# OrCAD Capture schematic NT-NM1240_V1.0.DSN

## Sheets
1 Nu-Link-ME V3.0: size A4; title: Nu-Link-Me; rev: 3.0; note: 1
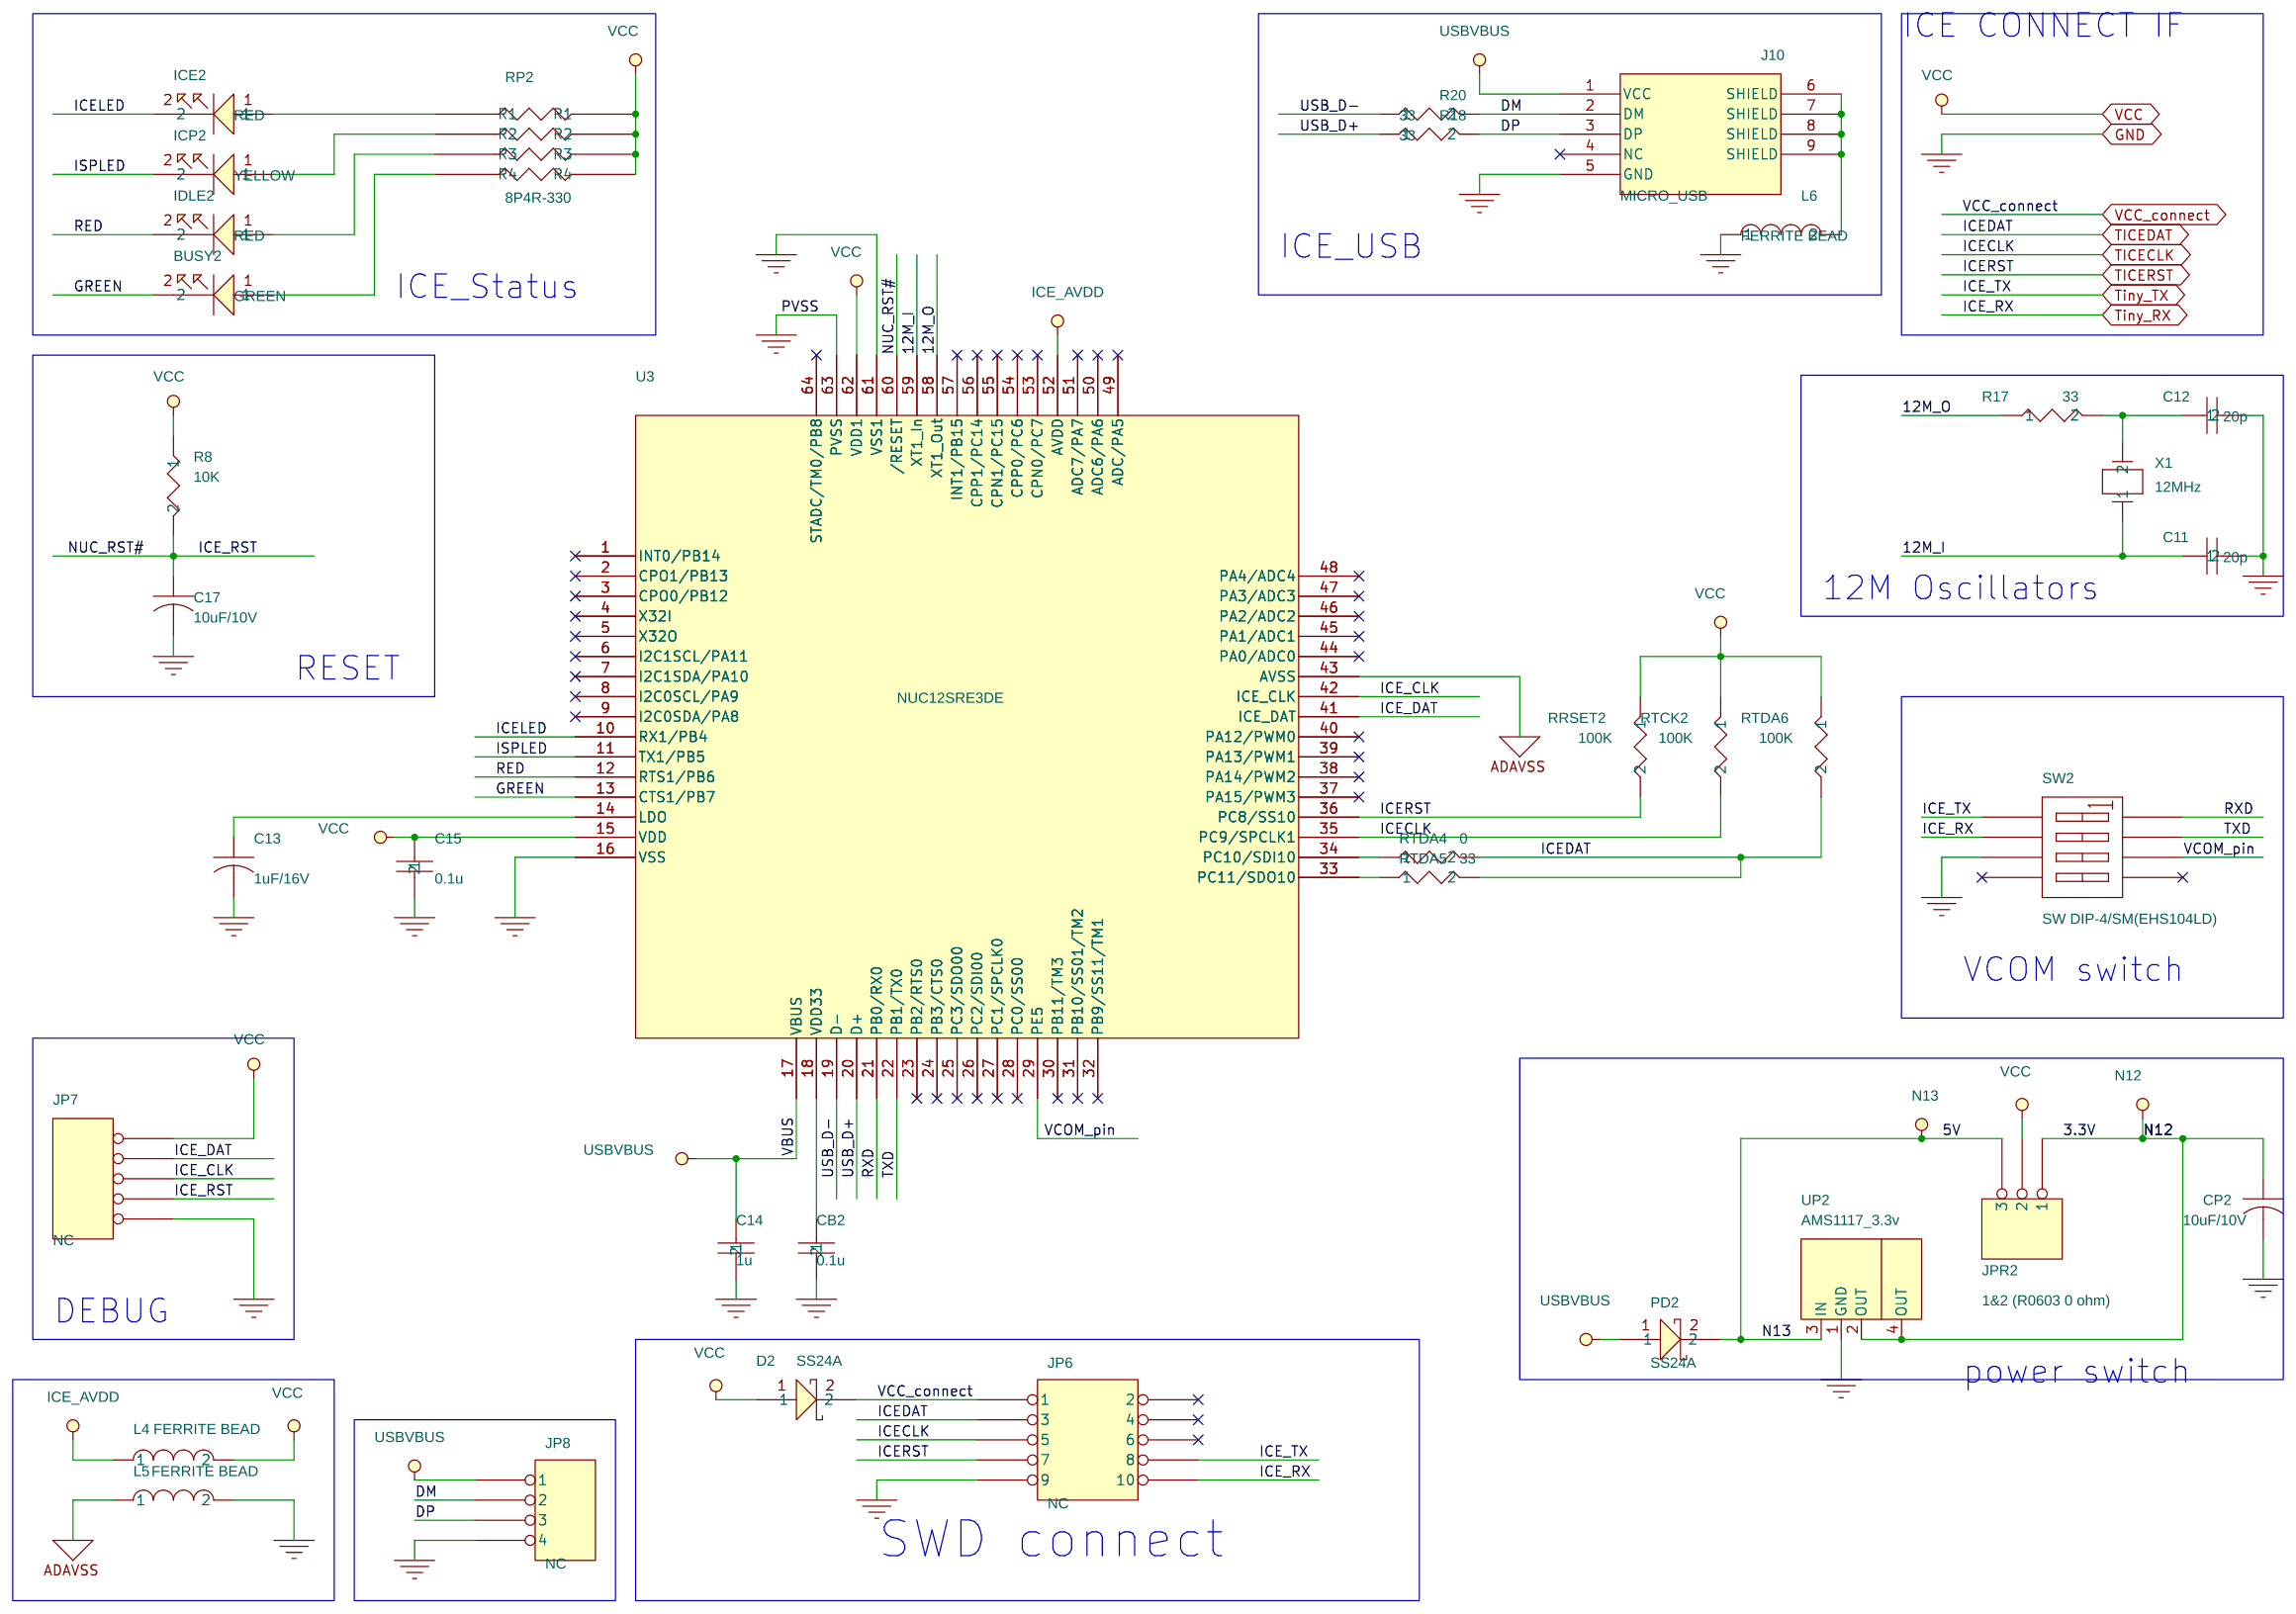
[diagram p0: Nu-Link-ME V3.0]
2 NuTiny-NM1240: size A3; title: NuTiny-EVB-NM1244D48; rev: V1.0
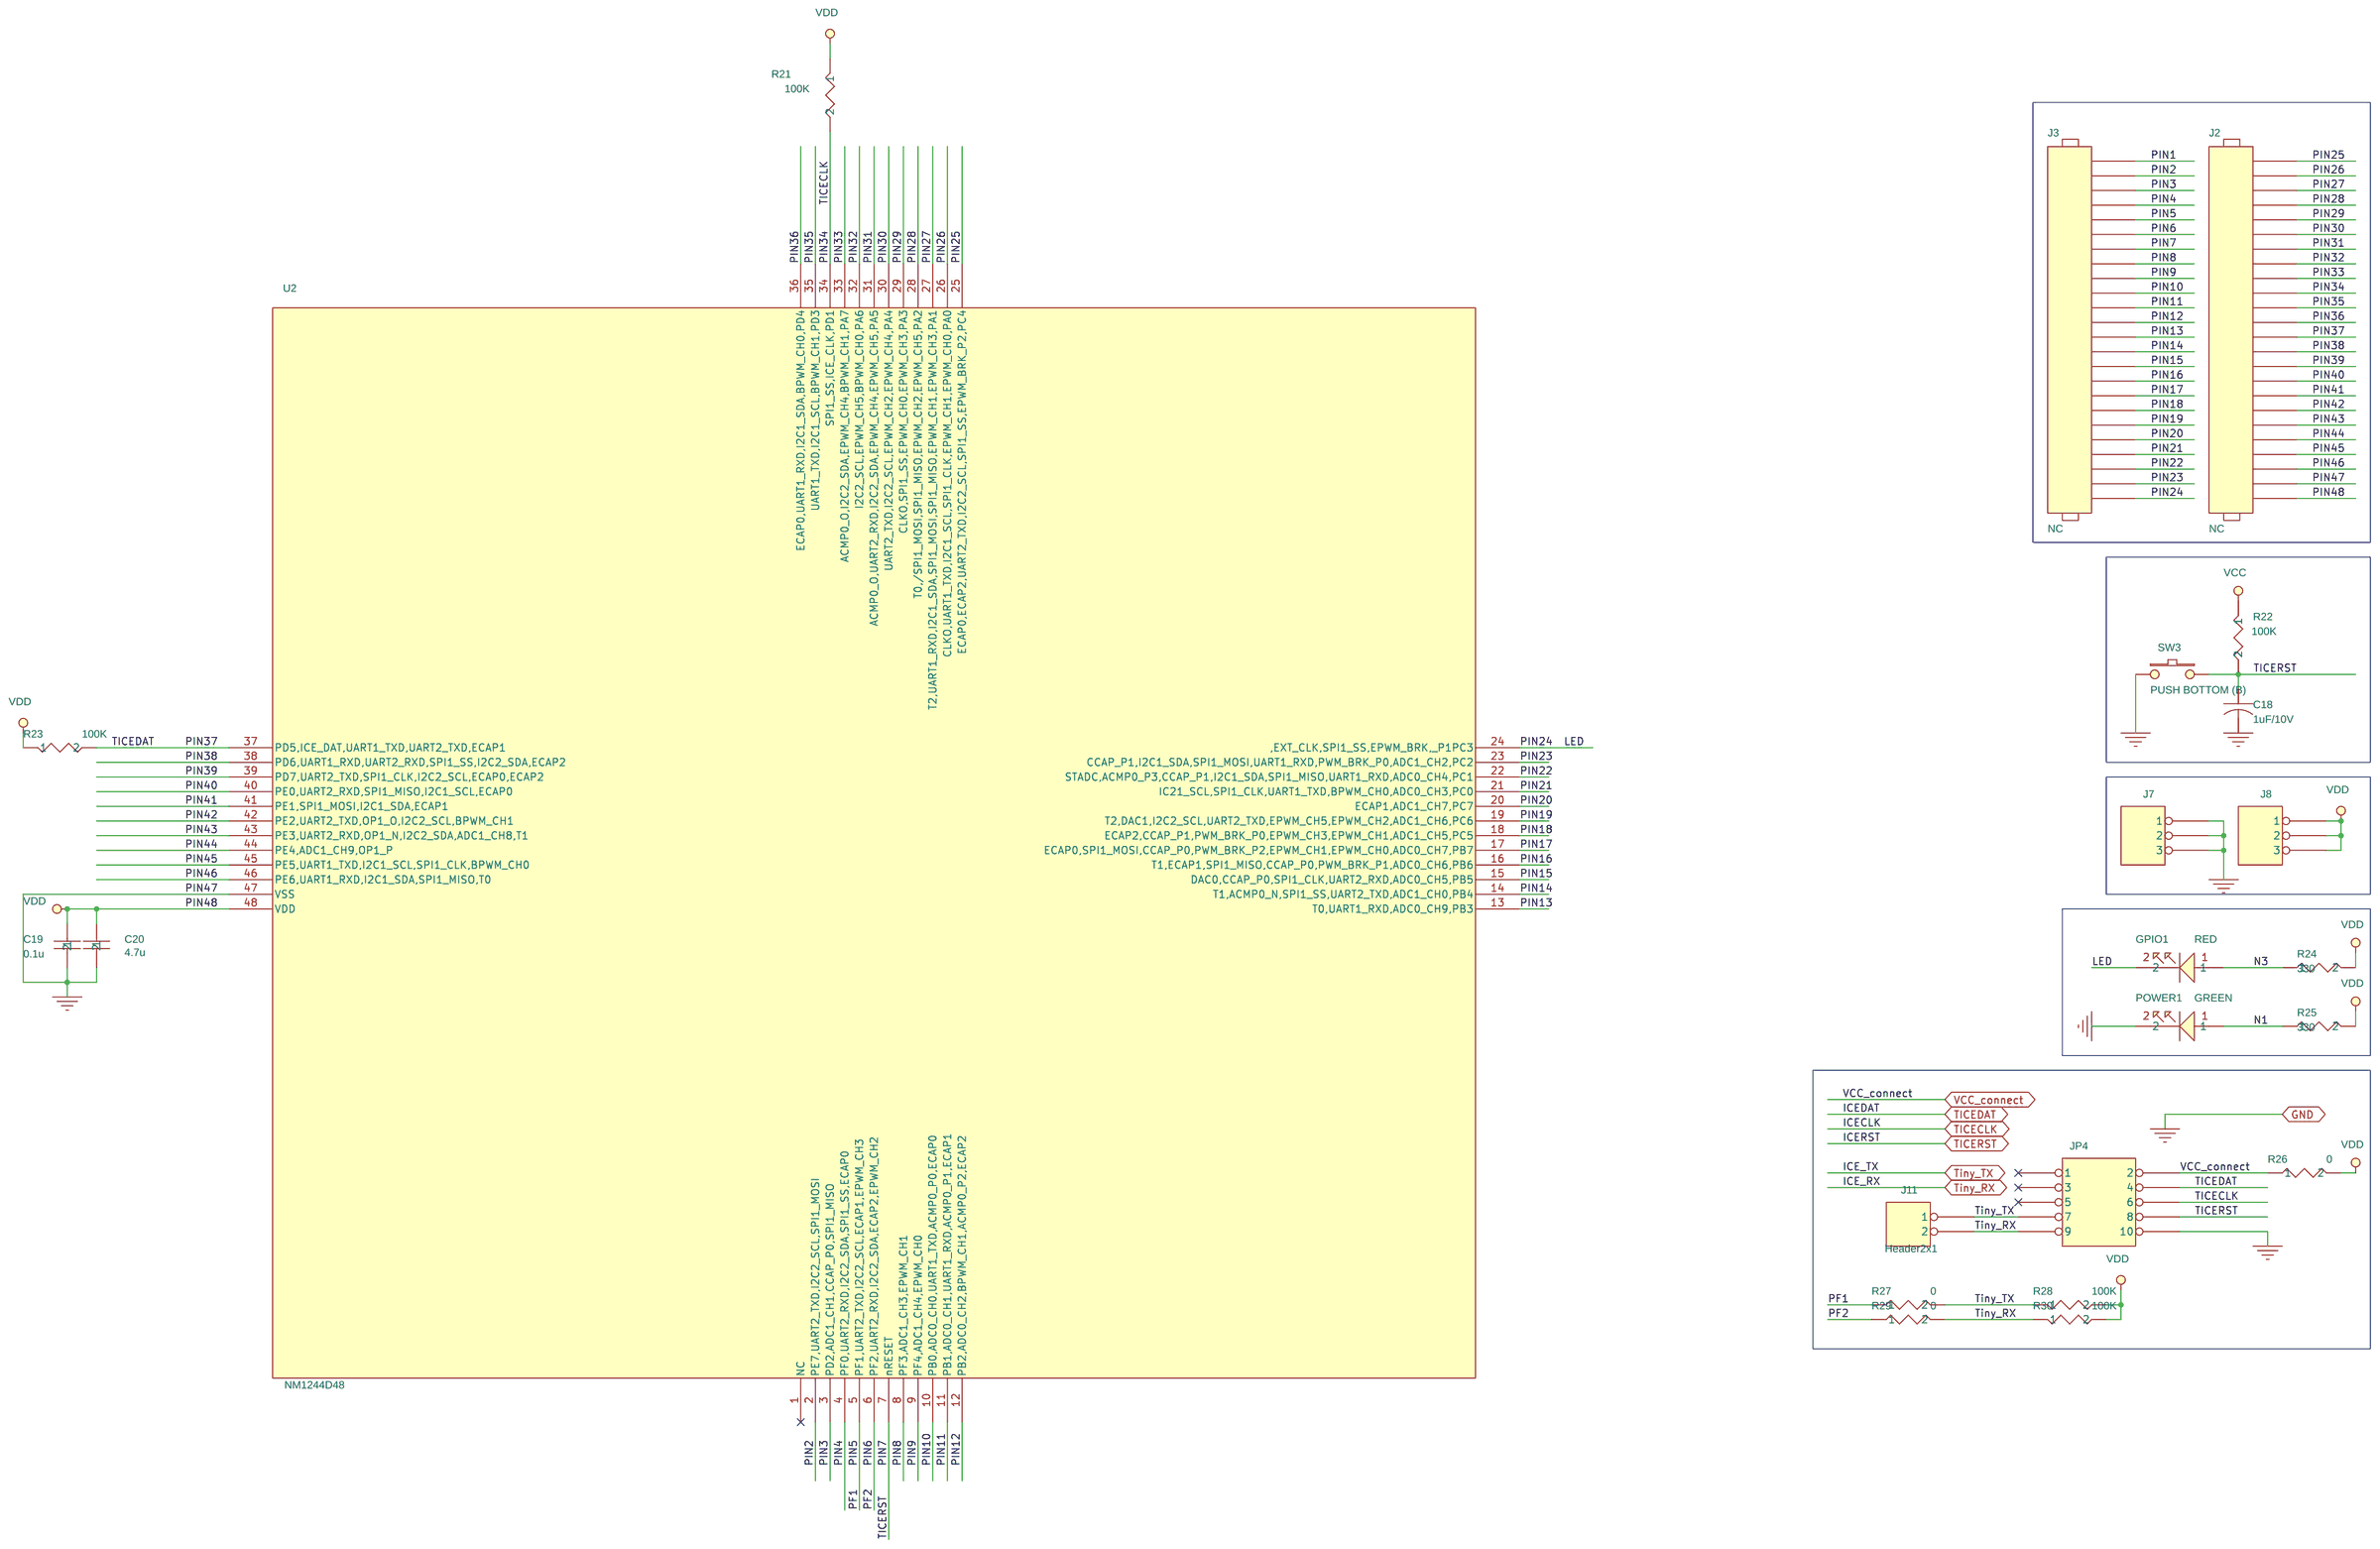
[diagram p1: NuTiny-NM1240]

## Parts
sheet Nu-Link-ME V3.0
BUSY2  GREEN  [LED0805]
C11  20p  [C0603]
C12  20p  [C0603]
C13  1uF/16V  [TANT-A]
C14  1u  [C0603]
C15  0.1u  [C0603]
C17  10uF/10V  [TANT-A]
CB2  0.1u  [C0603]
CP2  10uF/10V  [TANT-A]
D2  SS24A  [RB060L]
ICE2  RED  [LED0805]
ICP2  YELLOW  [LED0805]
IDLE2  RED  [LED0805]
J10  MICRO_USB  [MICRO_USB_AB_LS]
JP6  NC  [HEADER5X2]
JP7  NC  [HEADER05]
JP8  NC  [HEADER04]
JPR2  1&2 (R0603 0 ohm)  [R0603X2]
L4  FERRITE BEAD  [L0603]
L5  FERRITE BEAD  [L0603]
L6  FERRITE BEAD  [L0603]
PD2  SS24A  [RB060L]
R8  10K  [R0603]
R17  33  [R0603]
R18  33  [R0603]
R20  33  [R0603]
RP2  8P4R-330  [8P4RA]
RRSET2  100K  [R0603]
RTCK2  100K  [R0603]
RTDA4  0  [R0603]
RTDA5  33  [R0603]
RTDA6  100K  [R0603]
SW2  SW DIP-4/SM(EHS104LD)  [SW1X4]
U3  NUC12SRE3DE  [NCU120_LQFP_64]
UP2  AMS1117_3.3v  [SOT-223-1]
X1  12MHz  [XTAL\LP\SMD]
sheet NuTiny-NM1240
C18  1uF/10V  [TANT-A]
C19  0.1u  [C0603]
C20  4.7u  [C0603]
GPIO1  RED  [LED0805]
J2  NC  [HEADER24X1]
J3  NC  [HEADER24X1]
J7  NC  [header3]
J8  NC  [header3]
J11  Header2x1  [SIP-2P]
JP4  NC  [HEADER5X2]
POWER1  GREEN  [LED0805]
R21  100K  [R0603]
R22  100K  [R0603]
R23  100K  [R0603]
R24  330  [R0603]
R25  330  [R0603]
R26  0  [R0603]
R27  0  [R0603]
R28  100K  [R0603]
R29  0  [R0603]
R30  100K  [R0603]
SW3  PUSH BOTTOM (B)  [SW_SMD_HSM]
U2  NM1244D48  [LQFP-48]

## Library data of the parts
BUSY2 POWER1 = LED_GREEN
C11 = C_20p
C12 = C_20p_1
C13 = C_1uF_16V
C14 C20 = C_1u
C15 = C_0.1u_1
C17 C18 CP2 = C_10uF_10V
CB2 = C_0.1u
D2 = D_SS24A_1
ICE2 = LED_RED_1
ICP2 = LED_YELLOW
GPIO1 IDLE2 = LED_RED
J10 = mini_USB_5pin
JP4 JP6 = HEADER_5X2
JP7 = HEADER_5
JP8 = HEADER_4
J8 JPR2 = HEADER_3
L4 = FERRITE_BEAD
L5 = FERRITE_BEAD_2
L6 = FERRITE_BEAD_1
PD2 = D_SS24A
R8 = R_10K
R17 = R_33_3
R18 = R_33_1
R20 = R_33
RP2 = 8P4R-330
R30 RRSET2 = R_100K_1
R21 RTCK2 = R_100K_2
R29 RTDA4 = R_0
RTDA5 = R_33_2
R28 RTDA6 = R_100K
SW2 = SW_DIP-4_SM
U3 = NCU120_LQFP_1
UP2 = TO-247_Regulator_10
X1 = Xtal_12MHz
C19 = C_1u_1
J2 J3 = HEADER_24
J7 = HEADER_3_1
J11 = Header_0_ohm
R22 = R_100K_4
R23 = R_100K_3
R24 = R_1K
R25 = R_1K_1
R26 = R_0_2
R27 = R_0_1
SW3 = PUSH_BOTTOM_(B)
U2 = TF5103_4

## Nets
3.3V: CP2.1 JPR2.1 UP2.2(OUT) UP2.4(OUT)
5V: JPR2.3 PD2.2 UP2.3(IN)
AVSS: L5.1 U3.43(AVSS)
GND: C11.2 C12.2 C13.2 C14.2 C15.2 C17.2 C18.2 C19.2 C20.2 CB2.2 CP2.2 J2.23 J7.1 J7.2 J7.3 J10.5(GND) JP4.10 JP6.9 JP7.5 JP8.4 L5.2 L6.1 POWER1.2 SW2.3(A3) SW3.1 U2.47(VSS) U3.16(VSS) U3.61(VSS1) U3.63(PVSS) UP2.1(GND)
VCC: C15.1 D2.1 JP7.1 JPR2.2 L4.2 R8.1 RP2.2(R1) RP2.4(R2) RP2.6(R3) RP2.8(R4) RRSET2.1 RTCK2.1 RTDA6.1 U3.15(VDD) U3.62(VDD1)
VCC_connect: D2.2 JP4.2 JP6.1 R26.1
VDD: C19.1 C20.1 J2.24 J8.1 J8.2 J8.3 R21.1 R22.1 R23.1 R24.2 R25.2 R26.2 R28.2 R30.2 U2.48(VDD)
12M_I: C11.1 U3.59(XT1_In) X1.1
12M_O: R17.1 U3.58(XT1_Out)
DM: J10.2(DM) JP8.2 R20.2
DP: J10.3(DP) JP8.3 R18.2
GREEN: BUSY2.2 U3.13(CTS1/PB7)
ICE_AVDD: L4.1 U3.52(AVDD)
ICE_CLK: JP7.3 U3.42(ICE_CLK)
ICE_DAT: JP7.2 U3.41(ICE_DAT)
ICE_RST: C17.1 JP7.4 R8.2 U3.60(/RESET)
ICELED: ICE2.2 U3.10(RX1/PB4)
ICERST: C18.1 J3.18 JP4.8 JP6.7 R22.2 RRSET2.2 SW3.2 U2.7(nRESET) U3.36(PC8/SS10)
ISPLED: ICP2.2 U3.11(TX1/PB5)
LED: GPIO1.2 J3.1 U2.24(,EXT_CLK,SPI1_SS,EPWM_BRK,_P1PC3)
N1: POWER1.1 R25.1
N3: GPIO1.1 R24.1
PF1: J3.20 R27.1 U2.5(PF1,UART2_TXD,I2C2_SCL,ECAP1,EPWM_CH3)
PF2: J3.19 R29.1 U2.6(PF2,UART2_RXD,I2C2_SDA,ECAP2,EPWM_CH2)
PIN1: J3.24
PIN2: J3.23 U2.2(PE7,UART2_TXD,I2C2_SCL,SPI1_MOSI)
PIN3: J3.22 U2.3(PD2,ADC1_CH1,CCAP_P0,SPI1_MISO)
PIN4: J3.21 U2.4(PF0,UART2_RXD,I2C2_SDA,SPI1_SS,ECAP0)
PIN8: J3.17 U2.8(PF3,ADC1_CH3,EPWM_CH1)
PIN9: J3.16 U2.9(PF4,ADC1_CH4,EPWM_CH0)
PIN10: J3.15 U2.10(PB0,ADC0_CH0,UART1_TXD,ACMP0_P0,ECAP0)
PIN11: J3.14 U2.11(PB1,ADC0_CH1,UART1_RXD,ACMP0_P1,ECAP1)
PIN12: J3.13 U2.12(PB2,ADC0_CH2,BPWM_CH1,ACMP0_P2,ECAP2)
PIN13: J3.12 U2.13(T0,UART1_RXD,ADC0_CH9,PB3)
PIN14: J3.11 U2.14(T1,ACMP0_N,SPI1_SS,UART2_TXD,ADC1_CH0,PB4)
PIN15: J3.10 U2.15(DAC0,CCAP_P0,SPI1_CLK,UART2_RXD,ADC0_CH5,PB5)
PIN16: J3.9 U2.16(T1,ECAP1,SPI1_MISO,CCAP_P0,PWM_BRK_P1,ADC0_CH6,PB6)
PIN17: J3.8 U2.17(ECAP0,SPI1_MOSI,CCAP_P0,PWM_BRK_P2,EPWM_CH1,EPWM_CH0,ADC0_CH7,PB7)
PIN18: J3.7 U2.18(ECAP2,CCAP_P1,PWM_BRK_P0,EPWM_CH3,EPWM_CH1,ADC1_CH5,PC5)
PIN19: J3.6 U2.19(T2,DAC1,I2C2_SCL,UART2_TXD,EPWM_CH5,EPWM_CH2,ADC1_CH6,PC6)
PIN20: J3.5 U2.20(ECAP1,ADC1_CH7,PC7)
PIN21: J3.4 U2.21(IC21_SCL,SPI1_CLK,UART1_TXD,BPWM_CH0,ADC0_CH3,PC0)
PIN22: J3.3 U2.22(STADC,ACMP0_P3,CCAP_P1,I2C1_SDA,SPI1_MISO,UART1_RXD,ADC0_CH4,PC1)
PIN23: J3.2 U2.23(CCAP_P1,I2C1_SDA,SPI1_MOSI,UART1_RXD,PWM_BRK_P0,ADC1_CH2,PC2)
PIN25: J2.1 U2.25(ECAP0,ECAP2,UART2_TXD,I2C2_SCL,SPI1_SS,EPWM_BRK_P2,PC4)
PIN26: J2.2 U2.26(CLKO,UART1_TXD,I2C1_SCL,SPI1_CLK,EPWM_CH1,EPWM_CH0,PA0)
PIN27: J2.3 U2.27(T2,UART1_RXD,I2C1_SDA,SPI1_MOSI,SPI1_MISO,EPWM_CH1,EPWM_CH3,PA1)
PIN28: J2.4 U2.28(T0,/SPI1_MOSI,SPI1_MISO,EPWM_CH2,EPWM_CH5,PA2)
PIN29: J2.5 U2.29(CLKO,SPI1_SS,EPWM_CH0,EPWM_CH3,PA3)
PIN30: J2.6 U2.30(UART2_TXD,I2C2_SCL,EPWM_CH2,EPWM_CH4,PA4)
PIN31: J2.7 U2.31(ACMP0_O,UART2_RXD,I2C2_SDA,EPWM_CH4,EPWM_CH5,PA5)
PIN32: J2.8 U2.32(I2C2_SCL,EPWM_CH5,BPWM_CH0,PA6)
PIN33: J2.9 U2.33(ACMP0_O,I2C2_SDA,EPWM_CH4,BPWM_CH1,PA7)
PIN35: J2.11 U2.35(UART1_TXD,I2C1_SCL,BPWM_CH1,PD3)
PIN36: J2.12 U2.36(ECAP0,UART1_RXD,I2C1_SDA,BPWM_CH0,PD4)
PIN38: J2.14 U2.38(PD6,UART1_RXD,UART2_RXD,SPI1_SS,I2C2_SDA,ECAP2)
PIN39: J2.15 U2.39(PD7,UART2_TXD,SPI1_CLK,I2C2_SCL,ECAP0,ECAP2)
PIN40: J2.16 U2.40(PE0,UART2_RXD,SPI1_MISO,I2C1_SCL,ECAP0)
PIN41: J2.17 U2.41(PE1,SPI1_MOSI,I2C1_SDA,ECAP1)
PIN42: J2.18 U2.42(PE2,UART2_TXD,OP1_O,I2C2_SCL,BPWM_CH1)
PIN43: J2.19 U2.43(PE3,UART2_RXD,OP1_N,I2C2_SDA,ADC1_CH8,T1)
PIN44: J2.20 U2.44(PE4,ADC1_CH9,OP1_P)
PIN45: J2.21 U2.45(PE5,UART1_TXD,I2C1_SCL,SPI1_CLK,BPWM_CH0)
PIN46: J2.22 U2.46(PE6,UART1_RXD,I2C1_SDA,SPI1_MISO,T0)
RED: IDLE2.2 U3.12(RTS1/PB6)
RXD: SW2.8(B1) U3.21(PB0/RX0)
TICECLK: J2.10 JP4.6 JP6.5 R21.2 RTCK2.2 U2.34(SPI1_SS,ICE_CLK,PD1) U3.35(PC9/SPCLK1)
TICEDAT: J2.13 JP4.4 JP6.3 R23.2 RTDA4.2 RTDA5.2 RTDA6.2 U2.37(PD5,ICE_DAT,UART1_TXD,UART2_TXD,ECAP1)
Tiny_RX: J11.2 JP4.9 JP6.10 R29.2 R30.1 SW2.2(A2)
Tiny_TX: J11.1 JP4.7 JP6.8 R27.2 R28.1 SW2.1(A1)
TXD: SW2.7(B2) U3.22(PB1/TX0)
USB_D+: R18.1 U3.20(D+)
USB_D-: R20.1 U3.19(D-)
USBVBUS: C14.1 J10.1(VCC) JP8.1 PD2.1 U3.17(VBUS)
VCOM_pin: SW2.6(B3) U3.29(PE5)
N00874: BUSY2.1 RP2.7(R4)
N00882: IDLE2.1 RP2.5(R3)
N00906: ICE2.1 RP2.1(R1)
N00938: ICP2.1 RP2.3(R2)
N07793: C12.1 R17.2 X1.2
N16812063: C13.1 U3.14(LDO)
N16812255: CB2.1 U3.18(VDD33)
N16812376: RTDA5.1 U3.33(PC11/SDO10)
N17861502: RTDA4.1 U3.34(PC10/SDI10)
N18771284: J10.6(SHIELD) J10.7(SHIELD) J10.8(SHIELD) J10.9(SHIELD) L6.2

Not connected (* = marked no-connect by the designer): J10 4(NC)*; JP4 1* 3* 5*; JP6 2* 4* 6*; SW2 4(A4)* 5(B4)*; U2 1(NC)*; U3 1(INT0/PB14)* 2(CPO1/PB13)* 3(CPO0/PB12)* 4(X32I)* 5(X32O)* 6(I2C1SCL/PA11)* 7(I2C1SDA/PA10)* 8(I2C0SCL/PA9)* 9(I2C0SDA/PA8)* 23(PB2/RTS0)* 24(PB3/CTS0)* 25(PC3/SDO00)* 26(PC2/SDI00)* 27(PC1/SPCLK0)* 28(PC0/SS00)* 30(PB11/TM3)* 31(PB10/SS01/TM2)* 32(PB9/SS11/TM1)* 37(PA15/PWM3)* 38(PA14/PWM2)* 39(PA13/PWM1)* 40(PA12/PWM0)* 44(PA0/ADC0)* 45(PA1/ADC1)* 46(PA2/ADC2)* 47(PA3/ADC3)* 48(PA4/ADC4)* 49(ADC/PA5)* 50(ADC6/PA6)* 51(ADC7/PA7)* 53(CPN0/PC7)* 54(CPP0/PC6)* 55(CPN1/PC15)* 56(CPP1/PC14)* 57(INT1/PB15)* 64(STADC/TM0/PB8)*

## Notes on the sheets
sheet 1
- ICE CONNECT IF
- ICE_USB
- ICE_Status
- 12M Oscillators
- RESET
- VCOM switch
- DEBUG
- power switch
- SWD connect
